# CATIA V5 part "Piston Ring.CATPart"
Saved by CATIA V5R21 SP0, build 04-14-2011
Part number: Piston Ring
Bounding box of the stored display mesh (mm): x -46.5 to 46.5, y -46.442 to 46.335, z 0 to 3
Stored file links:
  D:\CATIA V5R21 E-RESOURCES\CATIA-V5R21\catia-v5r21-Prts\c13_catia_v5r21_prt\c13_catia_v5r21_figr_13-41\Part & Asm files\Piston Ring.CATPart
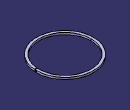
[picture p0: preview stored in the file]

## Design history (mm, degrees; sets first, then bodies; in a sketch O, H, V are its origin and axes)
Body1 (main body)
  Sketch1 on xy-plane, origin (0, 0, 0), H (1, 0, 0), V (0, 1, 0)
    circle A1 centre (0, 0) radius 46.5
    circle A2 centre (0, 0) radius 42.5
    radius A1 = 46.5
    radius A2 = 42.5
  Pad1: profile Sketch1, direction (0, 0, 1), length 3
  Sketch2 on yz-plane, origin (0, 0, 0), H (0, 1, 0), V (0, 0, 1)
    line L1 (2.5564, -3.2635) -> (-5.6312, 4.9241)
    line L2 (-5.6312, 4.9241) -> (-4.9241, 5.6312)
    line L3 (-4.9241, 5.6312) -> (3.2635, -2.5564)
    line L4 (3.2635, -2.5564) -> (2.5564, -3.2635)
    length L2 = 1
    distance O L1 = 0.5
    angle H L3 = 135
    parallelism: L4 L2, L1 L3
    perpendicularity: L1 L2
  Pocket1: profile Sketch2, direction (1, 0, 0), through (limit type 6)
